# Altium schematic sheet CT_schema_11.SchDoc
size 281 x 153 mm
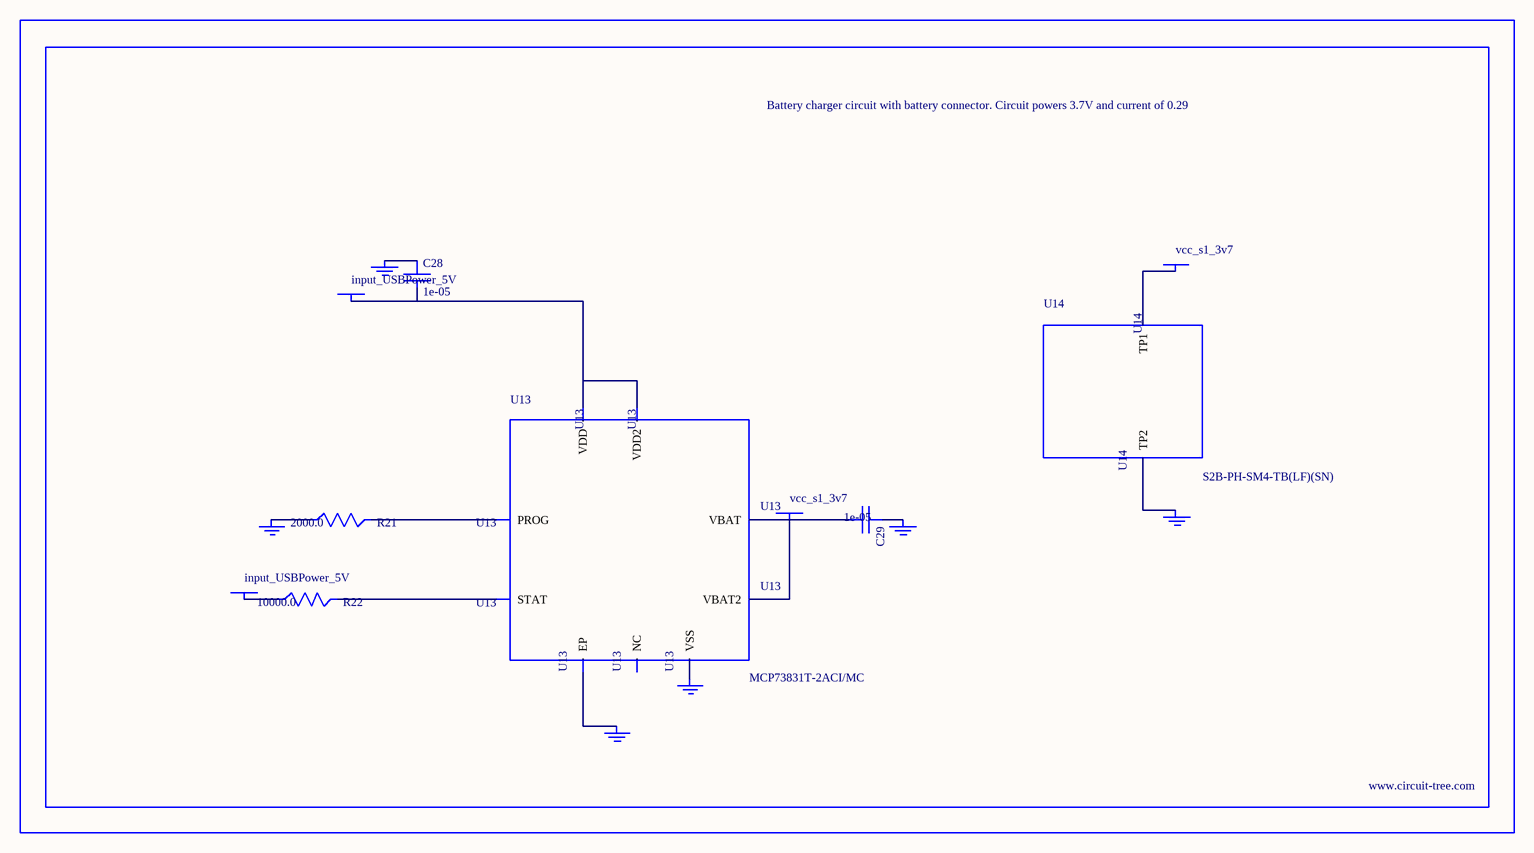
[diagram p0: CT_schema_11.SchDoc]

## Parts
BORDER10  (no value)
C28  1e-05  [C1206]
C29  1e-05  [C1206]
GND_INSTANCE_10_0  (no value)
GND_INSTANCE_10_1  (no value)
GND_INSTANCE_10_2  (no value)
GND_INSTANCE_10_3  (no value)
GND_INSTANCE_10_4  (no value)
GND_INSTANCE_10_5  (no value)
POWER_INSTANCE_10_0  input_USBPower_5V
POWER_INSTANCE_10_1  input_USBPower_5V
POWER_INSTANCE_10_2  vcc_s1_3v7
POWER_INSTANCE_10_3  vcc_s1_3v7
R21  2000.0  [R0603]
R22  10000.0  [R0603]
U13  MCP73831T-2ACI/MC  [DFN8_2X3MC]
U14  S2B-PH-SM4-TB(LF)(SN)  [JST-2-SMD]

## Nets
NetC28_1: C28.1 GND_INSTANCE_10_0.0(GND)
NetC28_2: C28.2 POWER_INSTANCE_10_0.0(PWR) U13.1(VDD) U13.2(VDD2)
NetC29_1: C29.1 GND_INSTANCE_10_1.0(GND)
NetC29_2: C29.2 POWER_INSTANCE_10_2.0(PWR) U13.3(VBAT) U13.4(VBAT2)
NetGND_INSTANCE_10_2_0: GND_INSTANCE_10_2.0(GND) R21.1
NetGND_INSTANCE_10_3_0: GND_INSTANCE_10_3.0(GND) U13.9(EP)
NetGND_INSTANCE_10_4_0: GND_INSTANCE_10_4.0(GND) U13.6(VSS)
NetGND_INSTANCE_10_5_0: GND_INSTANCE_10_5.0(GND) U14.2(TP2)
NetPOWER_INSTANCE_10_1_0: POWER_INSTANCE_10_1.0(PWR) R22.1
NetPOWER_INSTANCE_10_3_0: POWER_INSTANCE_10_3.0(PWR) U14.1(TP1)
NetR21_2: R21.2 U13.8(PROG)
NetR22_2: R22.2 U13.5(STAT)

Not connected (* = marked no-connect by the designer): U13 7(NC)

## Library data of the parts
BORDER10 = BORDER_PAGE10
C28 C29 = C1206C106K3RACTU
GND_INSTANCE_10_0-GND_INSTANCE_10_5 = GND
POWER_INSTANCE_10_0-POWER_INSTANCE_10_3 = PWR
R21 = RC0603JR-072KL
R22 = RC0603JR-0710KL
